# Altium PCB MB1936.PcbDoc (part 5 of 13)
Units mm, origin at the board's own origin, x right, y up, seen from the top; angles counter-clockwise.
Board outline 172 x 137 mm, 6 copper layers (Top Layer, Signal Layer 1, Signal Layer 2, Signal Layer 3, Signal Layer 4, Bottom Layer), stack 1.549 mm thick; 859 components, 672 nets, 3477 pads, 2222 vias.
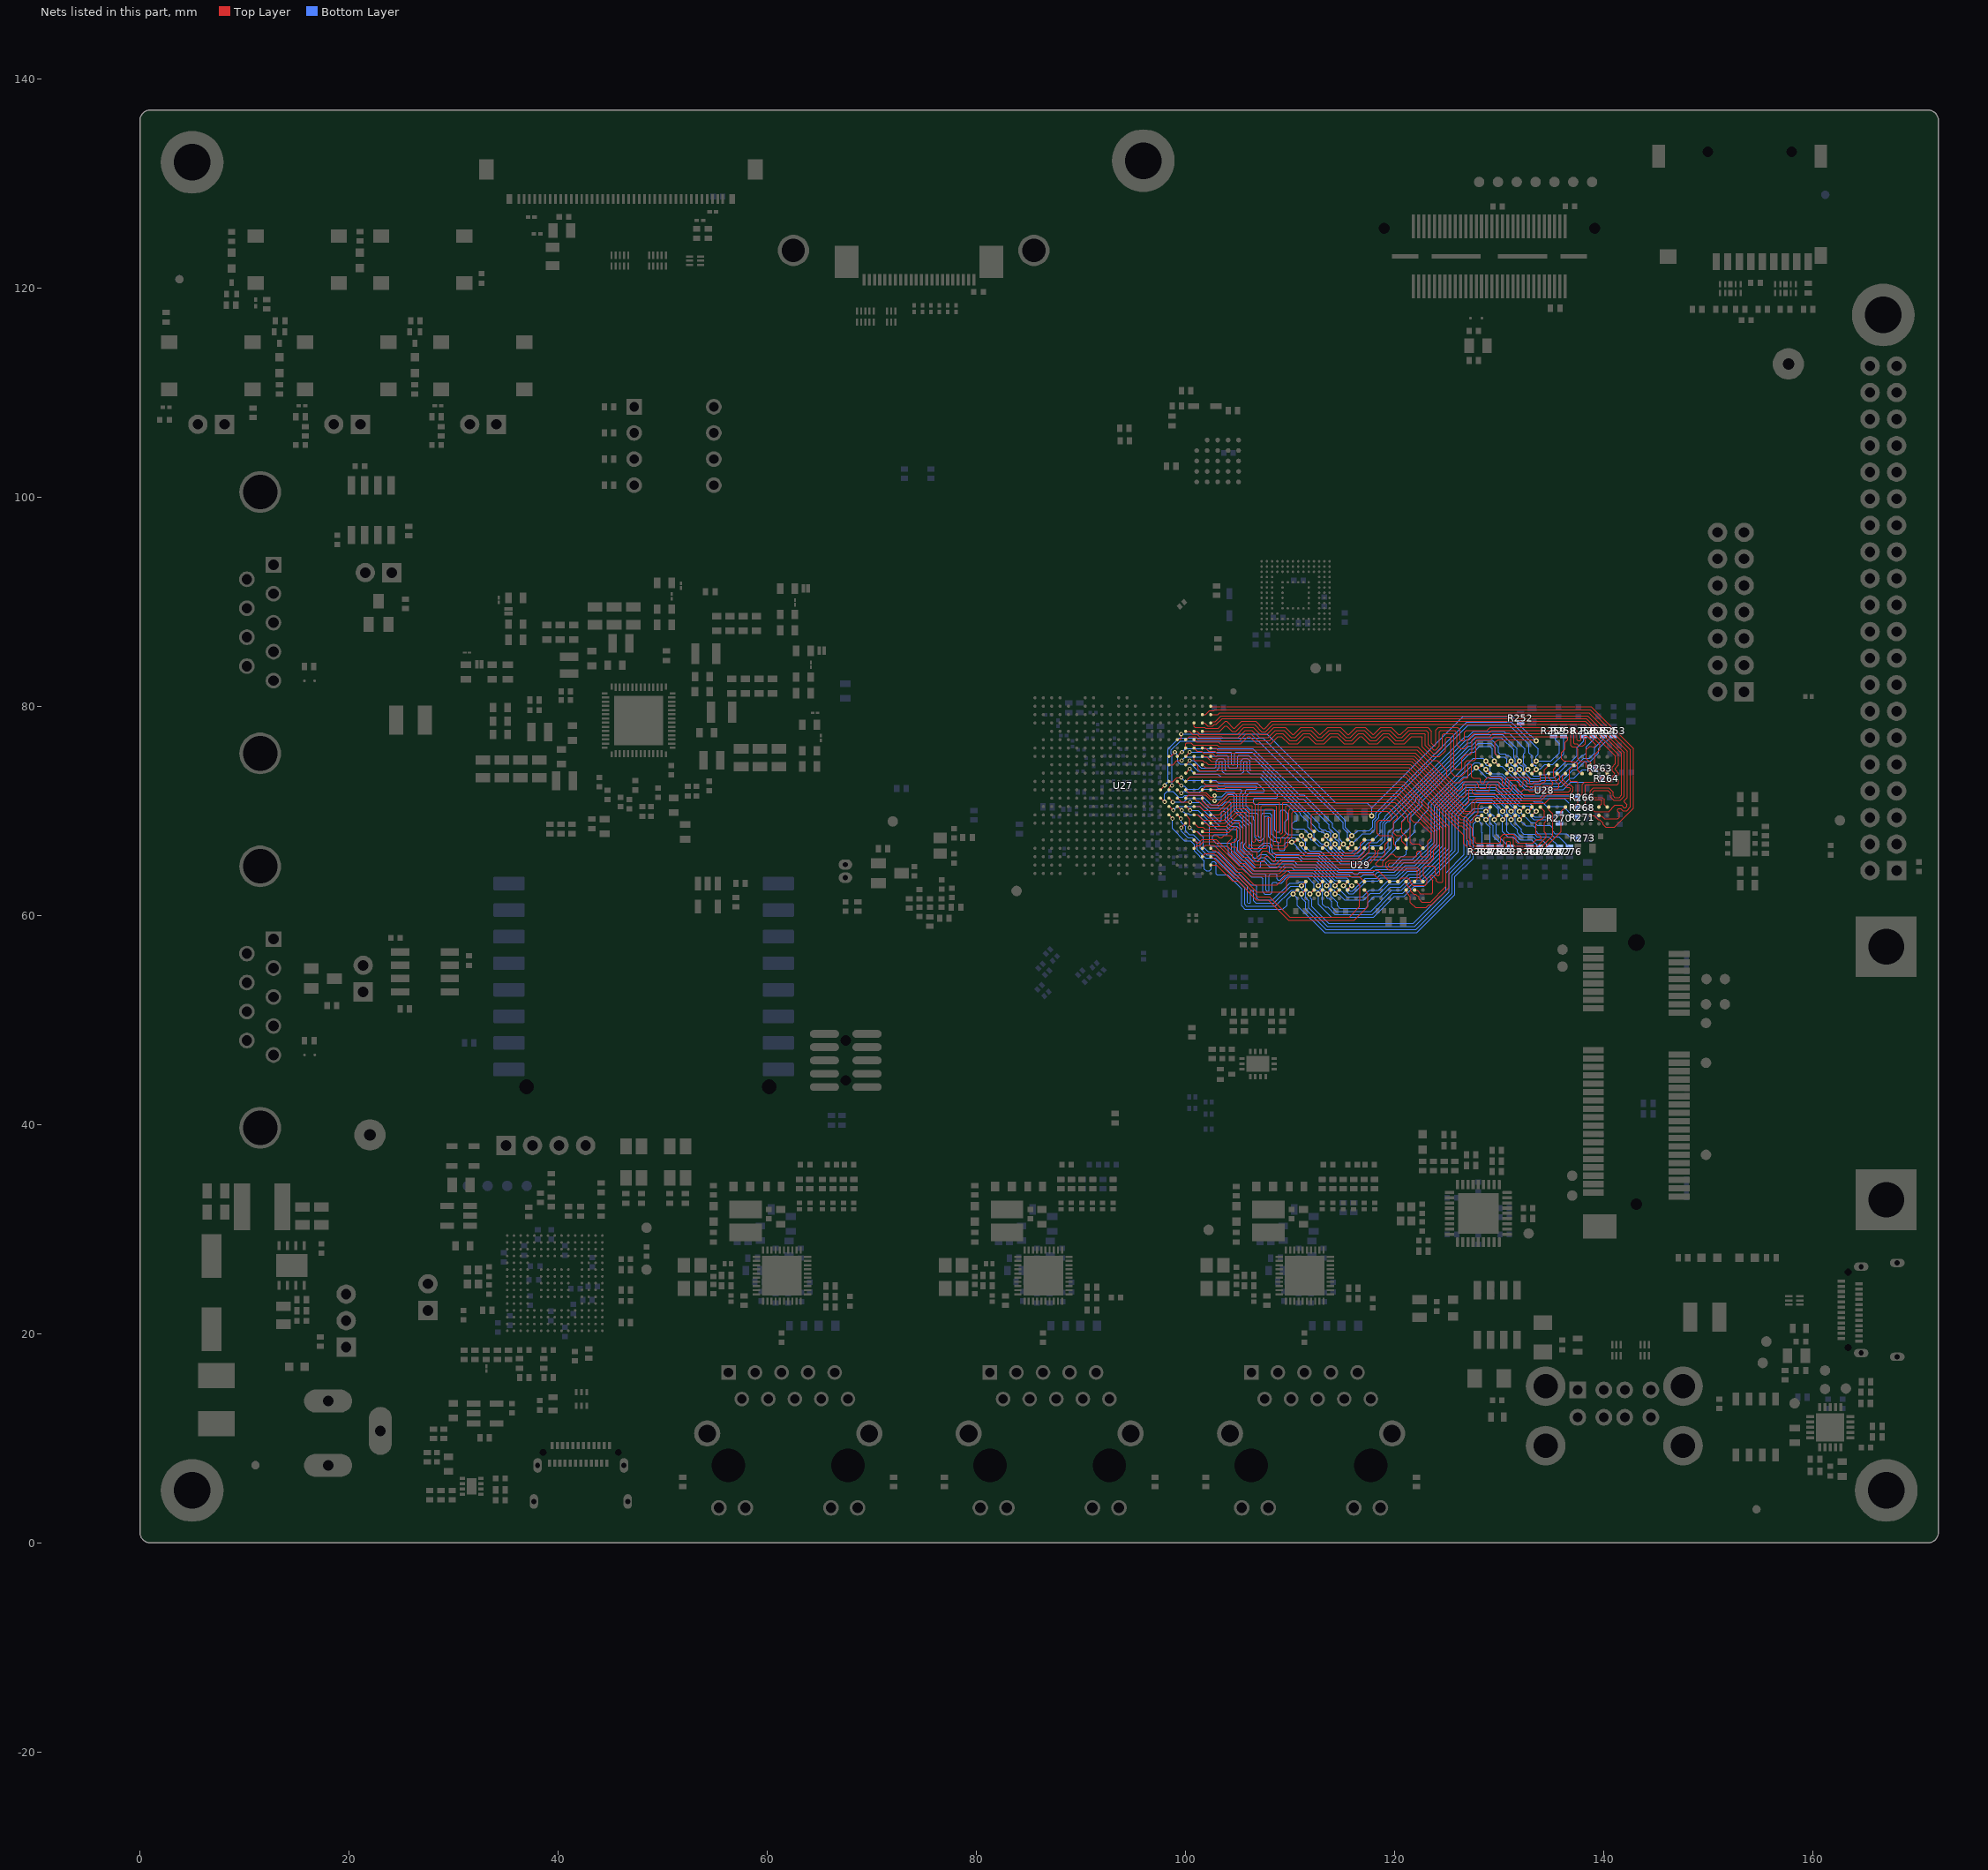
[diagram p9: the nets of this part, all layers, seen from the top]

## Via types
v1: diameter 0.55, hole 0.35, Top Layer to Bottom Layer, 1661 vias
v2: diameter 0.4, hole 0.2, Top Layer to Bottom Layer, tented both sides, 253 vias
v3: diameter 0.5, hole 0.2, Top Layer to Bottom Layer, 157 vias
v4: diameter 0.5, hole 0.25, Top Layer to Bottom Layer, 145 vias
v5: diameter 0.4, hole 0.2, Top Layer to Bottom Layer, 6 vias

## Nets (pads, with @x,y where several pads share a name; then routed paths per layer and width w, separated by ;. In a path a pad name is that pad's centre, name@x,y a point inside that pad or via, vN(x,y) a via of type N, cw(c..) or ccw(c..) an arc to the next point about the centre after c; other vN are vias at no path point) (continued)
DDR_A2: R268.1 U27.L18 U28.R3 U29.R3 | length 60.8
  Top Layer w0.09: U27.L18@99.2,72.8 v2(99.6,72.4) ; v4(111.1,66.825) 111.141,66.825 111.494,66.472 U29.R3@111.494,66.422 ; v4@128.732,73.928 128.772,73.928 129.125,73.575 U28.R3@129.125,73.55 U28.R3@129.125,73.525
  Bottom Layer w0.09: v2(99.6,72.4) 99.622,72.378 99.872,72.378 100.195,72.055 101.218,72.055 101.528,72.365 106.721,72.365 106.794,72.291 106.794,72.149 106.716,72.07 105.894,72.07 105.758,71.934 105.758,71.768 105.497,71.508 105.497,70.339 106.06,69.777 106.75,69.777 106.925,69.602 106.925,67.578 107.028,67.475 107.168,67.475 107.254,67.56 107.254,69.636 107.395,69.777 108.048,69.777 108.235,69.59 108.235,67.779 108.578,67.437 110.489,67.437 v4(111.1,66.825) 111.103,66.823 111.103,66.466 111.647,65.922 112.77,65.922 114.559,64.133 115.925,64.133 ; 115.925,64.132 116.116,63.94 116.457,63.94 116.65,64.133 117.958,64.133 118.21,64.385 ; 118.212,64.385 118.227,64.401 119.849,64.401 120.787,65.339 121.716,65.339 123.5,67.123 123.5,70.57 126.643,73.713 126.763,73.713 127.657,74.607 128.068,74.607 v4(128.725,73.95) 128.725,73.643 128.803,73.566 128.966,73.566 129.217,73.315 130.164,73.315 132.282,71.197 ; 132.28,71.195 136.23,71.195 137.125,70.3 R268.1@137.5,70.3
DDR_A3: R279.1 U27.P19 U28.N7 U29.N7 | length 56.9
  Top Layer w0.09: U27.P19@100,70.4 100.038,70.4 100.388,70.05 v2(100.425,70.05) ; v4(112.7,62.825) 112.724,62.825 113.094,63.195 U29.N7@113.094,63.222 ; v4@130.355,69.928 130.725,70.298 U28.N7@130.725,70.325
  Bottom Layer w0.09: v2(100.425,70.05) 101.175,70.05 102.992,68.234 103.762,68.234 103.993,68.003 103.993,67.765 103.94,67.713 102.738,67.713 102.575,67.55 102.575,67.25 102.898,66.927 104.298,66.927 104.415,66.81 104.415,65.963 106.421,63.958 107.549,63.958 107.679,63.828 107.679,62.403 107.759,62.322 107.922,62.322 107.975,62.375 107.975,63.81 108.123,63.958 108.606,63.958 108.725,63.839 108.725,63.481 108.822,63.384 109.037,63.384 109.49,63.837 112.024,63.837 112.7,63.161 v4(112.7,62.825) 112.7,62.775 112.9,62.575 112.9,62.384 113.104,62.18 113.104,61.046 113.37,60.78 113.595,60.78 114.275,60.1 117.854,60.1 119.854,62.1 120.773,62.1 121.731,63.059 122.66,63.059 125.781,66.18 125.781,69.627 127.244,71.09 129.246,71.09 130.325,70.011 v4(130.325,69.95) 130.325,69.9 130.513,69.713 130.513,69.588 130.6,69.5 130.6,69.434 130.72,69.314 130.72,68.021 130.939,67.803 131.443,67.803 132.021,67.225 133.086,67.225 133.376,66.935 133.389,66.935 133.39,66.934 133.417,66.934 133.825,66.525 R279.1@133.875,66.525
DDR_A4: R263.1 U27.H17 U28.N3 U29.N3 | length 60.3
  Top Layer w0.09: U27.H17@98.4,75.2 98.419,75.219 98.604,75.219 v2@98.98,75.595 ; U29.N3@113.094,66.422 113.094,66.47 113.449,66.825 v4(113.5,66.825) ; U28.N3@130.725,73.525 130.725,73.573 v4@131.08,73.928
  Bottom Layer w0.09: v2(98.98,75.6) 99.255,75.325 99.255,74.682 99.484,74.453 100.517,74.453 101.181,73.789 102.904,73.789 103.221,74.105 103.221,74.641 103.3,74.72 103.458,74.72 103.528,74.65 103.528,73.747 103.751,73.525 105.341,73.525 105.563,73.747 105.563,74.638 105.65,74.725 105.775,74.725 105.877,74.623 105.877,73.805 106.157,73.525 107.201,73.525 110.99,69.736 110.99,69.633 111.695,68.928 111.695,68.434 112.298,67.831 112.298,67.468 112.537,67.23 112.58,67.23 112.985,66.825 v4(113.5,66.825) 113.5,66.691 113.727,66.464 113.727,66.402 114.947,65.182 117.108,65.182 117.55,65.625 118.916,65.625 119.68,66.39 119.68,67.434 119.793,67.546 119.793,67.893 120.08,68.18 120.464,68.18 120.695,68.411 120.695,68.98 122.34,70.625 122.34,71.051 127.203,75.913 127.48,75.913 127.485,75.918 127.485,75.92 128,76.435 129.209,76.435 129.638,76.006 129.638,75.412 129.905,75.145 130.489,75.145 130.72,74.914 130.72,74.355 v4(131.125,73.95) 131.125,73.825 131.395,73.555 131.395,73.47 132.56,72.305 135.952,72.305 136.748,73.101 137.126,73.101 137.95,73.925 R263.1@139.2,73.925
DDR_A5: R282.1 U27.R19 U28.P8 U29.P8 | length 50.8
  Top Layer w0.09: U27.R19@100,69.6 100.4,69.2 v2(100.4,68.4) ; v4(111.9,62.025) 111.9,62.055 U29.P8@112.269,62.424 ; v4@129.532,69.158 U28.P8@129.901,69.527
  Bottom Layer w0.09: v2(100.4,68.4) 100.785,68.015 101.15,68.015 101.705,67.46 101.705,66.516 102.165,66.057 103.092,66.057 106.228,62.92 106.686,62.92 106.809,62.797 106.809,61.639 106.996,61.452 108.339,61.452 109.954,63.067 110.784,63.067 110.937,63.22 111.264,63.22 111.495,62.989 111.495,62.545 111.9,62.14 v4(111.9,62.025) 111.939,61.986 111.939,61.64 112.075,61.504 112.075,60.838 113.683,59.23 121.775,59.23 124.895,62.35 124.895,64.063 126.651,65.819 126.651,69.267 127.574,70.189 128.406,70.189 128.562,70.345 128.889,70.345 129.12,70.114 129.12,69.8 129.13,69.79 129.13,69.786 129.362,69.555 129.431,69.555 129.5,69.485 129.5,69.175 v4(129.525,69.15) 129.525,68.85 129.7,68.675 129.7,67.775 130.95,66.525 R282.1@131.025,66.525
DDR_A6: R264.1 U27.K19 U28.P2 U29.P2 | length 60.1
  Top Layer w0.09: U27.K19@100,73.6 v2(100.4,74) ; v4@111.896,67.62 112.269,67.247 112.294,67.247 112.375,67.166 112.35,67.166 U29.P2@112.294,67.222 ; v4@129.525,74.725 129.9,74.35 U28.P2@129.925,74.35
  Bottom Layer w0.09: v2(100.4,74) 100.4,73.99 100.891,73.499 103.108,73.499 103.372,73.235 107.081,73.235 108.8,71.516 108.8,71.292 108.708,71.2 106.6,71.2 106.5,71.1 106.5,70.747 106.6,70.647 109.669,70.647 110.7,69.616 110.7,69.096 110.648,69.043 110.488,69.043 110.199,68.754 110.199,68.412 110.361,68.25 111.315,68.25 v4@111.894,67.671 ; v4(111.9,67.625) 111.9,67.323 111.996,67.228 112.147,67.228 112.74,66.635 113.123,66.635 114.826,64.932 117.283,64.932 117.675,65.325 119.032,65.325 119.7,65.994 119.7,66 120.078,66.377 120.078,66.994 121.495,68.411 121.495,69.37 122.63,70.505 122.63,70.894 122.631,70.895 122.631,70.932 127.323,75.623 127.6,75.623 128.12,76.143 128.12,76.145 129.089,76.145 129.348,75.886 129.348,75.102 129.525,74.925 v4(129.525,74.75) 130.035,74.24 130.277,74.24 132.502,72.015 136.126,72.015 136.841,72.73 139.506,72.73 R264.1@139.75,72.975
DDR_A7: R275.1 U27.T19 U28.R8 U29.R8 | length 48.8
  Top Layer w0.09: v2(99.6,68.4) U27.T19@100,68.8 ; v4(111.1,62.025) U29.R8@111.5,62.425 ; v4@128.732,69.128 U28.R8@129.132,69.528
  Bottom Layer w0.09: v2(99.6,68.4) 99.607,68.393 99.607,68.059 100.231,67.435 100.628,67.435 101.125,66.938 101.125,66.276 101.924,65.477 102.823,65.477 105.649,62.65 105.649,61.035 105.812,60.872 108.587,60.872 ; 108.587,60.873 110.132,62.417 110.134,62.417 110.137,62.42 110.705,62.42 v4(111.1,62.025) ; v4@111.107,62.025 111.126,62.006 111.126,61.633 111.495,61.264 111.495,60.598 113.443,58.65 122.015,58.65 125.475,62.11 125.475,63.823 127.231,65.579 127.231,69.026 127.75,69.545 128.337,69.545 v4@128.725,69.157 ; v4@128.732,69.15 128.757,69.125 128.757,68.776 129.12,68.413 R275.1@129.12,66.53
  other v4: 128.725,69.15
DDR_A8: R266.1 U27.L17 U28.R2 U29.R2 | length 61.8
  Top Layer w0.09: U27.L17@98.4,72.8 98.783,72.8 99.158,73.175 v2(99.6,73.175) ; v4@111.094,67.622 U29.R2@111.494,67.222 ; v4@128.725,74.725 U28.R2@129.125,74.325
  Bottom Layer w0.09: v2(99.6,73.175) 99.856,72.919 102.868,72.919 103.132,72.655 106.841,72.655 107.525,71.971 107.525,71.833 107.473,71.78 106.18,71.78 105.787,71.388 105.787,70.46 106.18,70.067 108.458,70.067 108.525,70 108.525,68.156 108.694,67.988 108.975,67.988 109.075,68.088 109.075,69.967 109.175,70.067 109.429,70.067 109.805,69.691 109.805,69.23 109.519,68.944 109.519,68.027 109.814,67.732 110.873,67.732 110.983,67.622 v4@111.094,67.622 ; v4@111.14,67.576 111.14,67.293 111.213,67.22 111.264,67.22 111.5,66.984 111.5,66.525 111.854,66.172 112.873,66.172 114.662,64.383 117.693,64.383 118.001,64.691 119.716,64.691 120.655,65.63 120.864,65.63 121.105,65.871 121.105,66.189 121.175,66.259 121.175,67.25 121.905,67.98 121.905,68.589 122.038,68.721 122.038,68.788 122.55,69.3 122.55,69.465 123.21,70.125 123.21,70.654 123.211,70.655 123.211,70.691 127.538,75.018 128.433,75.018 128.7,74.75 128.7,74.425 128.775,74.35 128.957,74.35 129.13,74.176 129.13,73.77 129.345,73.555 130.263,73.555 132.372,71.446 136.654,71.446 136.85,71.25 R266.1@137.5,71.25
  other v4: 111.1,67.625 128.725,74.75
DDR_A9: R283.1 U27.R18 U28.R7 U29.R7 | length 52.8
  Top Layer w0.09: U27.R18@99.2,69.6 v2(99.55,69.25) ; v4(111.1,62.825) 111.494,63.218 U29.R7@111.494,63.222 ; v4@128.732,69.928 129.125,70.321 U28.R7@129.125,70.325
  Bottom Layer w0.09: v2(99.55,69.25) 99.595,69.205 99.595,68.9 100.026,68.47 100.026,68.05 100.346,67.73 100.66,67.73 100.665,67.725 100.749,67.725 101.415,67.058 101.415,66.396 102.044,65.767 102.943,65.767 105.939,62.77 105.939,61.236 106,61.175 106.169,61.175 106.221,61.228 ; 106.229,61.228 106.229,62.327 106.282,62.379 106.451,62.379 106.519,62.311 106.519,61.381 106.738,61.162 108.459,61.162 110.074,62.777 111.052,62.777 v4(111.1,62.825) 111.1,62.475 111.155,62.42 111.264,62.42 111.5,62.184 111.5,61.669 111.785,61.384 111.785,60.718 113.563,58.94 121.895,58.94 125.185,62.23 125.185,63.943 126.941,65.699 126.941,69.146 127.694,69.899 128.674,69.899 v4(128.725,69.95) ; v4@128.725,69.925 128.725,69.867 128.9,69.692 128.9,69.534 129.12,69.314 129.12,68.83 129.41,68.54 129.41,67.562 130.075,66.897 R283.1@130.075,66.525
DDR_A10: R254.1 U27.J17 U28.M3 U29.M3 | length 60.4
  Top Layer w0.09: U27.J17@98.4,74.4 98.783,74.4 99.183,74.8 v2(99.625,74.8) ; U29.M3@113.894,66.422 113.894,66.47 114.249,66.825 v4(114.3,66.825) ; U28.M3@131.525,73.55 131.525,73.573 v4@131.88,73.928
  Bottom Layer w0.09: v2(99.625,74.8) 99.632,74.8 99.977,75.145 102.361,75.145 102.433,75.217 102.977,75.217 103.06,75.3 103.933,75.3 104.108,75.125 104.108,74.2 104.204,74.105 104.886,74.105 104.983,74.203 104.983,75.2 105.088,75.305 106.016,75.305 106.348,74.973 106.573,74.973 112.805,68.741 112.805,68.411 113.037,68.18 113.34,68.18 113.5,68.02 113.68,68.02 113.903,67.798 113.903,67.304 114.263,66.943 114.263,66.825 v4(114.3,66.825) 114.3,66.536 115.154,65.682 116.653,65.682 117.621,66.65 118.575,66.65 119.1,67.175 119.1,68.745 119.325,68.97 119.509,68.97 121.76,71.221 121.76,71.291 126.963,76.493 127.238,76.493 127.76,77.015 130.179,77.015 131.39,75.804 131.39,75.441 131.391,75.043 131.52,74.914 131.52,74.53 131.75,74.3 131.75,74.2 131.925,74.025 v4(131.925,73.95) 131.925,73.836 132.22,73.541 132.22,73.466 132.851,72.835 133.987,72.835 134.037,72.885 135.554,72.885 136.864,74.195 137.255,74.195 138.075,75.015 138.599,75.015 139.12,75.536 139.12,76.034 139.95,76.864 R254.1@139.95,77.175
DDR_A11: R271.1 U27.M18 U28.T2 U29.T2 | length 59.6
  Top Layer w0.09: U27.M18@99.2,72 99.237,72 99.562,71.675 v2(99.6,71.675) ; v4(110.175,67) 110.423,67 110.647,67.224 U29.T2@110.694,67.224 ; v4@127.807,74.103 128.055,74.103 128.279,74.327 U28.T2@128.326,74.327
  Bottom Layer w0.09: v2(99.6,71.675) 99.6,71.677 99.79,71.867 99.973,71.867 100.089,71.751 101.324,71.751 101.648,72.075 105.226,72.075 105.375,71.925 105.375,71.796 105.207,71.628 105.207,70.219 105.94,69.487 106.405,69.487 106.52,69.372 106.52,69.168 106.635,69.053 106.635,67.458 106.908,67.185 107.288,67.185 107.579,67.475 107.579,69.402 107.664,69.487 107.858,69.487 107.945,69.4 107.945,67.505 108.35,67.1 108.75,67.1 108.855,66.995 108.855,66.376 109.015,66.215 109.412,66.215 109.519,66.322 109.519,66.856 109.662,67 v4(110.175,67) 110.216,67 110.625,66.59 110.625,66.507 111.46,65.672 112.666,65.672 114.455,63.883 115.625,63.883 115.858,63.65 116.782,63.65 117.015,63.883 118.118,63.883 118.33,64.095 ; 118.332,64.095 118.347,64.111 119.969,64.111 120.907,65.049 121.836,65.049 123.79,67.003 123.79,70.45 126.59,73.25 126.925,73.25 v4(127.8,74.125) 128.775,73.15 129,73.15 129.075,73.075 130.064,73.075 132.18,70.959 133.217,70.959 133.327,70.85 134.1,70.85 134.545,70.405 136.12,70.405 137.175,69.35 R271.1@137.5,69.35
DDR_A12: R277.1 U27.N18 U28.M7 U29.M7 | length 56.3
  Top Layer w0.09: U27.N18@99.2,71.2 99.575,70.825 v2(100.425,70.825) ; v4(113.5,62.825) 113.524,62.825 113.894,63.195 U29.M7@113.894,63.222 ; v4@131.132,69.928 131.155,69.928 131.525,70.298 U28.M7@131.525,70.325
  Bottom Layer w0.09: v2(100.425,70.825) 100.45,70.8 101.386,70.8 103.202,68.984 103.334,68.984 103.438,69.087 103.438,69.885 103.525,69.973 103.7,69.973 103.791,69.882 103.791,69.046 104.31,68.528 104.9,68.528 105.225,68.202 105.225,67.308 104.995,67.078 104.995,66.204 106.661,64.538 107.038,64.538 107.19,64.69 107.19,65.07 107.327,65.206 107.474,65.206 108.035,64.645 110.092,64.645 110.38,64.357 112.211,64.357 113.5,63.068 v4@113.5,62.882 ; v4(113.5,62.825) 113.711,62.614 113.711,62.373 113.895,62.189 113.895,61.84 114.505,61.23 114.505,60.911 114.737,60.68 117.214,60.68 117.45,60.916 117.45,61.234 118.042,61.825 118.704,61.825 119.579,62.7 120.553,62.7 121.491,63.639 122.42,63.639 125.2,66.419 125.2,69.866 127.004,71.67 129.488,71.67 131.125,70.033 v4(131.125,69.95) 131.35,69.725 131.35,69.556 131.522,69.385 131.522,68.795 132.105,68.211 132.105,67.986 132.337,67.755 133.377,67.755 133.617,67.515 133.629,67.515 133.63,67.514 134.746,67.514 135.735,66.525 R277.1@135.775,66.525
DDR_A13: R284.1 U27.R17 U28.T8 U29.T8 | length 51.4
  Top Layer w0.09: U27.R17@98.4,69.6 v2(98.75,69.25) ; v4(110.3,62.025) 110.3,62.055 U29.T8@110.669,62.424 ; v4@127.932,69.158 128.004,69.23 128.255,69.481 U28.T8@128.301,69.527
  Bottom Layer w0.09: v2(98.75,69.25) 98.75,68.29 99.895,67.145 100.456,67.145 100.835,66.765 100.835,66.156 101.804,65.187 101.804,64.422 101.985,64.242 102.274,64.242 102.453,64.42 102.453,64.976 102.602,65.125 102.764,65.125 102.907,64.982 102.907,63.977 103.017,63.867 104.022,63.867 105.359,62.53 105.359,60.908 105.685,60.582 109.315,60.582 109.698,60.965 109.698,61.503 110.22,62.025 v4(110.3,62.025) 110.705,61.62 110.705,60.936 113.282,58.36 122.135,58.36 125.765,61.99 125.765,63.703 127.521,65.459 127.521,68.734 127.925,69.138 v4(127.925,69.15) ; v4@127.925,69.125 128.323,68.728 128.323,67.936 128.375,67.884 128.375,66.725 R284.1@128.175,66.525
DDR_ACTN: R256.1 U27.H18 U28.L3 U29.L3 | length 55.5
  Top Layer w0.09: U27.H18@99.2,75.2 99.6,75.6 v2(99.65,75.6) ; U29.L3@114.694,66.422 114.694,66.47 115.049,66.825 v4(115.1,66.825) ; U28.L3@132.325,73.525 132.325,73.573 v4@132.68,73.928
  Bottom Layer w0.09: v2@99.658,75.6 100.003,75.945 106.429,75.945 110.879,71.495 111.313,71.495 114.055,68.753 114.055,68.429 114.703,67.781 114.703,67.279 115.1,66.882 115.1,66.755 115.656,66.2 116.288,66.2 117.318,67.23 117.944,67.23 118.618,67.904 118.618,68.838 119.084,69.304 119.084,69.435 126.722,77.073 126.998,77.073 127.52,77.595 130.42,77.595 130.598,77.417 130.942,77.417 132.47,75.889 132.47,75.561 132.325,75.416 132.325,74.517 132.56,74.282 132.56,74.177 132.725,74.012 v4(132.725,73.95) 132.725,73.852 133.262,73.315 133.788,73.315 133.948,73.475 134.475,73.475 134.703,73.703 135.361,73.703 136.433,74.775 136.919,74.775 137.425,75.281 137.425,76.024 138.05,76.65 R256.1@138.05,77.175
DDR_BA0: R253.1 U27.J19 U28.N2 U29.N2 | length 60.7
  Top Layer w0.09: U27.J19@100,74.4 v2(100.4,74.8) ; U29.N2@113.094,67.222 113.094,67.27 v4@113.424,67.6 ; U28.N2@130.725,74.325 130.725,74.373 v4@131.055,74.703
  Bottom Layer w0.09: v2(100.4,74.8) 100.409,74.791 100.756,74.791 101.468,74.079 102.784,74.079 102.931,74.225 102.931,74.761 103.18,75.01 103.578,75.01 103.818,74.77 103.818,73.94 103.943,73.815 105.166,73.815 105.273,73.922 105.273,74.758 105.53,75.015 105.895,75.015 106.167,74.743 106.167,73.925 106.277,73.815 107.322,73.815 111.985,69.151 111.985,68.804 112.77,68.02 112.928,68.02 112.958,67.99 113.135,67.99 v4(113.5,67.625) ; v4@113.5,67.6 113.5,67.322 113.603,67.22 113.664,67.22 113.901,66.983 113.901,66.666 114.05,66.516 114.05,66.433 115.051,65.432 116.862,65.432 117.383,65.952 118.833,65.952 119.39,66.51 119.39,67.906 119.905,68.421 119.905,68.81 122.05,70.955 122.05,71.171 127.083,76.203 127.358,76.203 127.88,76.725 129.329,76.725 129.928,76.126 129.928,75.572 130.05,75.45 130.542,75.45 130.662,75.33 130.871,75.33 131.101,75.1 131.101,74.923 131.125,74.899 v4(131.125,74.75) 131.125,74.425 131.205,74.345 131.289,74.345 131.52,74.114 131.52,73.78 132.705,72.595 135.744,72.595 137.054,73.905 137.376,73.905 138.196,74.725 138.719,74.725 139.512,75.518 139.512,75.933 140.15,76.572 140.15,76.59 140.235,76.675 140.299,76.675 140.799,77.175 R253.1@140.9,77.175
DDR_BA1: R280.1 U27.P18 U28.N8 U29.N8 | length 53.6
  Top Layer w0.09: U27.P18@99.2,70.4 99.237,70.4 99.588,70.05 v2(99.625,70.05) ; v4(112.7,62.025) 112.7,62.055 U29.N8@113.069,62.424 ; v4@130.332,69.158 U28.N8@130.701,69.527
  Bottom Layer w0.09: v2(99.625,70.05) 99.648,70.05 99.974,69.724 100.264,69.724 100.38,69.607 101.208,69.607 102.285,68.53 102.285,66.756 102.405,66.637 103.928,66.637 104.125,66.44 104.125,65.843 106.301,63.668 107.22,63.668 107.389,63.499 107.389,62.214 107.571,62.032 108.099,62.032 108.265,62.198 108.265,63.04 108.375,63.15 108.646,63.15 108.702,63.094 109.157,63.094 109.71,63.647 111.637,63.647 112.299,62.985 112.299,62.531 112.428,62.402 112.613,62.402 112.7,62.315 v4(112.7,62.025) 112.7,61.033 113.924,59.81 117.974,59.81 119.974,61.81 120.893,61.81 121.852,62.769 122.78,62.769 126.071,66.06 126.071,69.507 127.365,70.8 129.234,70.8 129.92,70.114 129.92,69.796 130.162,69.555 130.245,69.555 130.3,69.5 130.3,69.175 v4(130.325,69.15) 130.325,68.006 130.832,67.5 131.335,67.5 131.9,66.935 132.44,66.935 132.85,66.525 R280.1@132.925,66.525
DDR_BG0: R255.1 U27.H19 U28.M2 U29.M2 | length 57.6
  Top Layer w0.09: U27.H19@100,75.2 v2(100.4,75.6) ; U29.M2@113.894,67.222 113.894,67.27 114.249,67.625 v4(114.3,67.625) ; U28.M2@131.525,74.325 131.525,74.373 v4@131.88,74.728
  Bottom Layer w0.09: v2(100.4,75.6) 104.298,75.6 104.398,75.5 104.398,74.479 104.482,74.395 104.612,74.395 104.693,74.476 104.693,75.468 104.825,75.6 106.357,75.6 110.832,71.125 111.233,71.125 113.703,68.655 113.703,68.303 v4@114.341,67.666 ; v4(114.3,67.625) 114.3,67.306 114.387,67.22 114.464,67.22 114.7,66.984 114.7,66.49 115.258,65.932 116.463,65.932 117.471,66.94 118.315,66.94 118.857,67.482 118.857,68.798 126.843,76.783 127.118,76.783 127.64,77.305 130.299,77.305 131.68,75.924 131.68,75.561 ; 131.681,75.561 131.681,75.163 131.81,75.034 131.81,74.976 131.925,74.861 v4(131.925,74.75) 131.925,74.47 132.045,74.35 132.139,74.35 132.32,74.168 132.32,73.786 132.317,73.783 133.025,73.075 133.888,73.075 133.988,73.175 135.244,73.175 136.554,74.485 137.135,74.485 137.955,75.305 138.089,75.305 138.32,75.536 138.32,76.107 139,76.787 R255.1@139,77.175
DDR_CASN: R278.1 U27.P17 U28.M8 U29.M8 | length 53.7
  Top Layer w0.09: U27.P17@98.4,70.4 98.45,70.4 98.8,70.05 v2@98.85,70.05 ; v4(113.5,62.025) 113.5,62.055 U29.M8@113.869,62.424 ; v4@131.132,69.158 U28.M8@131.501,69.527
  Bottom Layer w0.09: v2@98.85,70.05 99.2,70.4 101.376,70.4 103.252,68.524 103.904,68.524 104.19,68.238 104.78,68.238 104.935,68.082 104.935,67.439 104.705,67.209 104.705,66.084 106.541,64.248 109.797,64.248 109.95,64.095 112.12,64.095 113.095,63.119 113.095,62.557 v4@113.441,62.211 ; v4@113.449,62.203 v4@113.441,62.211 ; R278.1@134.825,66.525 134.788,66.525 134.089,67.224 133.51,67.224 133.509,67.225 133.497,67.225 133.207,67.515 132.141,67.515 131.753,67.903 131.725,67.93 131.725,68.175 131.125,68.775 v4(131.125,69.15) 131.132,69.156 131.132,69.506 131.083,69.555 130.962,69.555 130.73,69.786 130.73,69.795 130.72,69.805 130.72,70.134 129.474,71.38 127.124,71.38 125.49,69.746 125.49,66.299 122.54,63.349 121.611,63.349 120.653,62.39 119.734,62.39 117.734,60.39 114.395,60.39 113.997,60.789 113.997,61.287 113.664,61.62 113.555,61.62 113.5,61.675 v4(113.5,62.025) 113.441,62.084 v4@113.441,62.211
  other v2: 98.825,70.05
DDR_CKE: R259.1 U27.M16 U28.K2 U29.K2 | length 57.3
  Top Layer w0.09: U27.M16@97.6,72 97.6,72.012 98,72.413 v2(98,72.425) ; U29.K2@115.5,67.225 v4(115.9,67.625) ; U28.K2@133.132,74.357 v4(133.525,74.75)
  Bottom Layer w0.09: v2(98,72.425) 98.345,72.77 98.345,75.92 99.386,76.961 107.381,76.961 115.278,69.064 115.278,68.398 115.9,67.776 v4(115.9,67.625) 115.975,67.625 116.45,68.1 117.584,68.1 117.9,68.416 117.9,69.065 118.215,69.379 118.215,69.796 126.896,78.477 131.132,78.477 133.72,75.889 133.72,75.392 133.525,75.197 v4(133.525,74.75) 134.965,74.75 135.75,75.535 135.75,76.4 135.375,76.775 135.375,77 R259.1@135.2,77.175
DDR_CLK_N: R270.2 U27.M19 U28.K8 U29.K8 | length 53.7
  Top Layer w0.09: U27.M19@100,72 100.295,71.705 101.964,71.705 102.369,71.3 102.625,71.3 v2(102.775,71.45) ; U29.K8@115.494,62.422 115.494,62.472 115.847,62.825 v4(115.9,62.825) ; U28.K8@133.125,69.525 U28.K8@133.125,69.55 133.125,69.575 133.478,69.928 v4@133.532,69.928
  Bottom Layer w0.09: v2(102.775,71.45) 102.859,71.45 102.981,71.328 103.454,71.328 103.91,71.785 104.607,71.785 104.917,71.475 104.917,70.099 106.345,68.671 106.345,66.508 106.489,66.365 106.9,66.365 107.435,66.9 108.025,66.9 108.287,66.638 108.287,66.089 108.563,65.813 110.813,65.813 111.243,65.383 112.6,65.383 114.397,63.586 115.411,63.586 115.616,63.38 115.616,63.03 115.794,62.852 115.794,62.764 115.614,62.584 115.614,62.427 115.729,62.312 115.96,62.312 117.201,63.553 118.301,63.553 118.569,63.821 120.089,63.821 121.027,64.759 121.956,64.759 124.08,66.883 124.08,70.33 126.54,72.79 129.915,72.79 131.986,70.719 132.938,70.719 133.232,70.425 133.232,70.22 133.502,69.95 v4(133.525,69.95) 133.25,69.675 133.25,69.534 133.388,69.396 135.392,69.396 135.721,69.725 R270.2@135.75,69.725
DDR_CLK_P: R270.1 U27.N19 U28.K7 U29.K7 | length 53.6
  Top Layer w0.09: U27.N19@100,71.2 100.325,71.525 101.89,71.525 102.315,71.1 102.625,71.1 v2(102.775,70.95) ; v4(115.1,62.825) 115.147,62.825 115.494,63.172 U29.K7@115.494,63.222 ; v4@132.778,69.928 133.125,70.275 U28.K7@133.125,70.325
  Bottom Layer w0.09: v2(102.775,70.95) 102.855,70.95 102.983,71.078 103.557,71.078 104.014,71.535 104.504,71.535 104.667,71.371 104.667,69.996 106.095,68.568 106.095,66.405 106.385,66.115 107.004,66.115 107.539,66.65 107.921,66.65 108.037,66.535 108.037,65.985 108.459,65.563 110.709,65.563 111.139,65.133 112.496,65.133 114.293,63.336 115.307,63.336 115.366,63.277 115.366,63.03 v4@115.194,62.857 ; v4(115.1,62.825) 115.127,62.825 115.364,62.589 115.364,62.324 115.625,62.062 116.063,62.062 117.304,63.303 118.404,63.303 118.672,63.571 120.193,63.571 121.131,64.509 122.06,64.509 124.33,66.779 124.33,70.227 126.644,72.54 129.811,72.54 131.882,70.469 132.834,70.469 132.982,70.321 132.982,70.206 v4(132.725,69.95) 133,69.675 133,69.43 133.285,69.146 135.382,69.146 135.703,68.825 R270.1@135.75,68.825
DDR_CSN: R273.1 U27.N16 U28.L7 U29.L7 | length 57.9
  Top Layer w0.09: U27.N16@97.6,71.2 97.625,71.2 97.975,70.85 v2(98,70.85) ; v4(114.3,62.825) 114.332,62.825 114.669,63.163 U29.L7@114.669,63.224 ; v4@131.963,69.928 132.301,70.266 U28.L7@132.301,70.327
  Bottom Layer w0.09: v2(98,70.85) 98,71.6 98.25,71.85 98.8,71.85 99.352,71.298 99.779,71.298 99.941,71.46 101.546,71.46 102.453,70.553 103.528,70.553 103.8,70.825 104.25,70.825 104.371,70.704 104.371,69.286 104.55,69.108 105.14,69.108 105.805,68.443 105.805,66.98 105.575,66.75 105.575,66.444 106.54,65.479 106.78,65.479 107.125,65.825 107.675,65.825 108.275,65.225 110.332,65.225 110.7,64.857 112.418,64.857 114.3,62.975 v4(114.3,62.825) 114.3,62.775 114.65,62.425 114.754,62.425 115.407,61.772 116.937,61.772 117.57,62.405 118.464,62.405 119.339,63.28 120.312,63.28 121.251,64.219 122.18,64.219 124.62,66.659 124.62,70.106 126.764,72.25 129.653,72.25 131.368,70.535 131.911,69.991 131.911,69.978 131.925,69.964 v4(131.925,69.95) 133.036,68.839 133.4,68.839 133.632,68.607 134.35,68.607 ; 134.35,68.606 134.853,68.606 135.095,68.364 135.095,68.046 135.337,67.805 136.42,67.805 136.85,67.375 R273.1@137.55,67.375
DDR_DQ0: U27.W22 U29.F7 | length 18.5
  Top Layer w0.09: U27.W22@102.4,66.4 102.615,66.185 102.82,66.185 104.862,64.144 105.339,64.144 106.556,62.927 108.753,62.927 109.836,64.01 117.908,64.01 U29.F7@118.682,63.237
DDR_DQ1: U27.Y21 U29.H7 | length 18.5
  Top Layer w0.09: U27.Y21@101.6,65.6 101.6,65.628 101.867,65.895 102.7,65.895 104.741,63.854 105.219,63.854 106.826,62.246 109.511,62.246 109.669,62.405 109.669,63.377 110.012,63.72 116.596,63.72 U29.H7@117.094,63.222
DDR_DQ2: U27.Y22 U29.J7 | length 19.6
  Top Layer w0.09: U27.Y22@102.4,65.6 102.419,65.581 102.604,65.581 104.621,63.564 105.098,63.564 106.884,61.778 108.022,61.778 109.953,59.847 115.648,59.847 116.651,60.851 116.651,61.417 116.695,61.461 116.695,62.82 U29.J7@116.294,63.222
DDR_DQ3: U27.AA22 U29.H8 | length 19.5
  Top Layer w0.09: U27.AA22@102.4,64.8 102.975,64.8 104.501,63.274 104.978,63.274 106.764,61.488 107.902,61.488 109.843,59.547 116.149,59.547 117.453,60.851 117.453,62.063 U29.H8@117.094,62.422
DDR_DQ4: U27.T21 U29.J3 | length 20
  Top Layer w0.09: U27.T21@101.6,68.8 101.942,68.8 102.237,68.505 103.899,68.505 104.992,69.599 105.381,69.599 105.501,69.478 105.501,66.319 105.686,66.134 106.676,66.134 106.835,65.974 106.835,65.53 106.934,65.432 107.071,65.432 107.232,65.593 107.232,65.957 107.413,66.137 107.785,66.137 108.072,65.85 108.382,65.85 108.536,66.003 115.875,66.003 U29.J3@116.294,66.422
DDR_DQ5: U27.T20 U29.H2 | length 22.2
  Top Layer w0.09: U27.T20@100.8,68.8 101.182,68.418 101.67,68.418 101.873,68.215 104.019,68.215 104.777,68.973 105.038,68.973 105.139,68.872 105.139,68.517 105.211,68.445 105.211,66.198 105.566,65.844 106.371,65.844 106.423,65.791 106.423,65.463 106.744,65.142 107.523,65.142 107.576,65.195 107.576,65.527 107.706,65.658 107.848,65.658 108.364,65.142 108.498,65.142 108.612,65.256 108.612,65.628 108.697,65.713 116.104,65.713 116.735,66.345 116.735,66.864 U29.H2@117.094,67.222
DDR_DQ6: U27.U21 U29.H3 | length 20.3
  Top Layer w0.09: U27.U21@101.604,68.004 101.682,67.925 104.139,67.925 104.682,68.468 104.778,68.468 104.921,68.325 104.921,67.221 104.7,67 104.463,67 104.315,66.852 104.315,66.684 104.462,66.537 104.773,66.537 104.888,66.422 104.888,66.111 105.446,65.554 105.923,65.554 106.624,64.852 108.618,64.852 109.189,65.423 116.482,65.423 117.094,66.035 U29.H3@117.094,66.422
DDR_DQ7: U27.U20 U29.G2 | length 21.4
  Top Layer w0.09: U27.U20@100.8,68 101.078,68 101.452,67.626 103.005,67.626 103.231,67.4 103.475,67.4 103.7,67.626 104.375,67.626 104.428,67.573 104.428,67.375 104.025,66.972 104.025,66.564 105.326,65.264 105.803,65.264 106.504,64.562 108.738,64.562 109.309,65.133 116.602,65.133 117.544,66.074 117.544,66.872 U29.G2@117.894,67.222
DDR_DQ8: U27.M21 U29.B8 | length 35.2
  Top Layer w0.09: U27.M21@101.6,72 101.903,72.303 102.947,72.303 103.083,72.168 103.776,72.168 103.826,72.217 120.651,72.217 124.615,68.253 124.615,63.246 124.515,63.146 124.15,63.146 123.994,63.303 123.994,63.472 123.614,63.852 123.54,63.852 123.378,63.69 123.378,63.616 123.645,63.349 123.645,62.17 123.55,62.075 122.461,62.075 122.151,62.386 121.93,62.386 U29.B8@121.894,62.422
DDR_DQ9: U27.M22 U29.D7 | length 35.2
  Top Layer w0.09: U27.M22@102.4,72 102.84,72 102.963,71.878 103.896,71.878 103.946,71.927 103.961,71.927 120.531,71.927 124.325,68.133 124.325,63.934 124.185,63.794 124.082,63.794 123.893,63.982 123.893,64.552 123.715,64.73 122.952,64.73 122.769,64.547 122.769,63.797 123.094,63.471 123.094,63.063 122.908,62.877 121.751,62.877 121.474,63.154 121.474,63.339 121.241,63.573 120.644,63.573 U29.D7@120.294,63.222
DDR_DQ10: U27.L21 U29.C7 | length 36.4
  Top Layer w0.09: U27.L21@101.6,72.8 101.9,72.5 103.16,72.5 103.203,72.458 103.656,72.458 103.706,72.507 120.771,72.507 124.905,68.373 124.905,62.771 123.411,61.277 122.596,61.277 122.321,61.552 122.321,61.708 122.007,62.022 121.806,62.022 121.521,62.307 121.521,62.523 121.094,62.951 U29.C7@121.094,63.222
DDR_DQ11: U27.L22 U29.C8 | length 36.5
  Top Layer w0.09: U27.L22@102.403,72.797 120.891,72.797 125.195,68.493 125.195,62.651 123.531,60.987 123.257,60.987 123.025,60.755 121.984,60.755 121.984,60.758 121.507,61.234 121.507,61.777 121.15,62.134 121.15,62.375 U29.C8@121.1,62.425
DDR_DQ12: U27.T22 U29.D3 | length 35.7
  Top Layer w0.09: U27.T22@102.4,68.8 103.783,68.8 104.872,69.889 105.737,69.889 105.791,69.835 105.791,66.585 105.949,66.427 107.716,66.427 107.827,66.538 107.827,69.263 107.91,69.347 108.01,69.347 108.123,69.233 108.123,66.54 108.296,66.367 109.46,66.367 109.78,66.687 109.78,67.164 110.164,67.547 110.164,69.788 110.313,69.937 119.279,69.937 119.719,69.497 119.719,69.239 119.587,69.108 118.533,69.108 118.305,68.88 118.305,67.858 118.541,67.622 119.665,67.622 119.924,67.363 119.924,66.792 U29.D3@120.294,66.422
DDR_DQ13: U27.R20 U29.C3 | length 37.4
  Top Layer w0.09: U27.R20@100.8,69.6 101.138,69.6 101.636,69.102 103.675,69.102 104.765,70.192 105.844,70.192 106.081,69.955 106.081,66.825 106.188,66.717 107.424,66.717 107.537,66.83 107.537,70.029 107.653,70.145 108.296,70.145 108.413,70.028 108.413,66.754 108.51,66.657 109.34,66.657 109.49,66.807 109.49,67.284 109.874,67.667 109.874,70.049 110.052,70.227 119.483,70.227 120.263,69.447 120.269,69.447 120.269,69.337 119.902,68.97 119.902,67.875 120.149,67.628 120.538,67.628 120.694,67.472 120.694,67.085 121.08,66.698 121.08,66.436 U29.C3@121.094,66.422
DDR_DQ14: U27.R21 U29.C2 | length 36.8
  Top Layer w0.09: U27.R21@101.6,69.6 101.893,69.6 102.189,69.304 103.346,69.304 104.56,70.517 106.284,70.517 106.371,70.431 106.371,67.089 106.453,67.007 106.566,67.007 106.661,67.102 106.661,67.233 106.737,67.309 106.852,67.309 106.957,67.204 106.957,67.082 107.031,67.007 107.158,67.007 107.247,67.096 107.247,70.431 107.333,70.517 108.633,70.517 108.703,70.447 108.703,67.035 108.791,66.947 109.031,66.947 109.121,67.037 109.121,67.358 109.584,67.821 109.584,70.439 109.662,70.517 119.769,70.517 120.994,69.292 120.994,69.186 120.704,68.897 120.704,67.924 121.094,67.534 U29.C2@121.094,67.222
DDR_DQ15: U27.R22 U29.A3 | length 35.9
  Top Layer w0.09: U27.R22@102.4,69.6 103.232,69.6 104.44,70.807 106.441,70.807 106.661,70.587 106.661,67.682 106.743,67.599 106.876,67.599 106.957,67.68 106.957,70.705 107.059,70.807 108.94,70.807 108.993,70.754 108.993,67.867 109.046,67.814 109.167,67.814 109.294,67.941 109.294,70.754 109.346,70.807 120.01,70.807 121.286,69.532 121.286,68.986 121.495,68.776 121.495,66.99 121.665,66.82 122.296,66.82 U29.A3@122.694,66.422
DDR_DQ16: U27.D20 U28.D7 | length 52.3
  Top Layer w0.09: U27.D20@100.8,78.4 100.8,78.074 100.912,77.962 ; 100.913,77.963 101.838,77.963 101.908,77.892 103.143,77.892 103.791,78.54 103.925,78.54 104.573,77.892 104.712,77.892 105.36,78.54 106.715,78.54 107.399,77.856 107.546,77.856 108.231,78.54 138.22,78.54 141.412,75.348 141.412,74.373 ; U28.D7@137.925,70.35 137.925,70.366 138.23,70.67 138.23,72.412 138.282,72.465 141.261,72.465 141.413,72.617 141.413,72.863 141.236,73.04 141.236,73.285 141.413,73.462 141.413,73.593 141.093,73.913 141.093,74.052 141.413,74.372
DDR_DQ17: U27.C22 U28.C7 | length 50.9
  Top Layer w0.09: U27.C22@102.4,79.2 103.106,79.2 103.277,79.37 138.564,79.37 142.243,75.691 142.243,71.27 141.949,70.976 141.949,70.826 142.191,70.585 142.191,70.427 142.067,70.304 141.924,70.304 141.703,70.525 141.072,70.525 140.468,69.921 139.13,69.921 U28.C7@138.725,70.325
DDR_DQ18: U27.C21 U28.B8 | length 52.6
  Top Layer w0.09: U27.C21@101.6,79.2 101.897,79.2 102.272,79.575 102.725,79.575 102.811,79.66 138.684,79.66 142.533,75.812 142.533,70.359 142.188,70.014 141.804,70.014 141.631,70.187 141.402,70.187 141.318,70.103 141.318,69.932 141.47,69.78 141.47,69.366 141.332,69.228 140.047,69.228 139.78,69.495 139.58,69.495 U28.B8@139.525,69.55
DDR_DQ19: U27.B22 U28.C8 | length 53.2
  Top Layer w0.09: U27.B22@102.4,80 102.45,79.95 138.804,79.95 139.04,79.715 142.823,75.932 142.823,70.239 141.014,68.43 140.193,68.43 139.93,68.693 139.93,68.798 139.568,69.16 139.463,69.16 139.073,69.55 U28.C8@138.725,69.55
DDR_DQ20: U27.F20 U28.D3 | length 54.2
  Top Layer w0.09: U27.F20@100.8,76.8 101.025,76.575 103.14,76.575 103.309,76.406 105.277,76.406 105.961,77.09 106.115,77.09 106.799,76.406 108.147,76.406 108.831,77.09 109.181,77.09 109.865,76.406 110.711,76.406 111.395,77.09 111.74,77.09 112.424,76.406 113.261,76.406 113.945,77.09 114.465,77.09 115.149,76.406 115.986,76.406 116.67,77.09 116.843,77.09 117.527,76.406 118.352,76.406 119.036,77.09 119.305,77.09 119.989,76.406 120.936,76.406 121.62,77.09 122.6,77.09 122.646,77.045 122.646,76.1 123.574,75.172 124.284,75.172 124.865,75.753 124.865,76.89 125,77.025 125.225,77.025 125.376,76.875 125.376,73.68 125.721,73.335 126.42,73.335 126.7,73.615 126.7,74.601 126.925,74.825 127.6,74.825 127.755,74.98 127.755,76.67 127.881,76.796 129.196,76.796 129.49,77.09 136.46,77.09 136.545,77.005 136.545,76.795 136.3,76.55 136.3,75.9 135.95,75.55 135.95,74.96 136.15,74.761 136.786,74.761 136.852,74.695 137.323,74.695 137.47,74.548 137.47,73.897 137.818,73.55 U28.D3@137.925,73.55
DDR_DQ21: U27.F19 U28.C3 | length 54.6
  Top Layer w0.09: U27.F19@100,76.8 100.039,76.8 100.339,77.1 100.924,77.1 101.199,76.825 103.3,76.825 103.429,76.696 105.157,76.696 105.841,77.38 106.235,77.38 106.919,76.696 108.027,76.696 108.711,77.38 109.301,77.38 109.985,76.696 110.591,76.696 111.275,77.38 111.86,77.38 112.544,76.696 113.141,76.696 113.825,77.38 114.585,77.38 115.269,76.696 115.866,76.696 116.55,77.38 116.963,77.38 117.647,76.696 118.232,76.696 118.916,77.38 119.425,77.38 120.109,76.696 120.816,76.696 121.5,77.38 122.821,77.38 122.936,77.265 122.936,76.22 123.694,75.462 123.962,75.462 124.575,76.075 124.575,77.25 124.706,77.38 125.52,77.38 125.666,77.235 125.666,74.1 125.816,73.95 126.285,73.95 126.41,74.075 126.41,74.993 126.793,75.375 127.25,75.375 127.4,75.525 127.4,76.75 127.736,77.086 129.076,77.086 129.37,77.38 136.745,77.38 136.835,77.29 136.835,76.785 ; 136.835,76.765 136.835,76.24 136.98,76.095 137.289,76.095 137.52,75.864 137.52,75.848 137.527,75.842 137.527,75.644 137.528,75.642 137.528,74.983 137.537,74.974 137.537,74.964 137.768,74.733 137.778,74.733 137.781,74.73 138.161,74.73 138.325,74.566 138.325,74.188 138.712,73.801 U28.C3@138.712,73.539
DDR_DQ22: U27.E19 U28.C2 | length 54
  Top Layer w0.09: U27.E19@100,77.6 100.376,77.6 100.676,77.3 101.117,77.3 101.317,77.1 103.435,77.1 103.549,76.986 105.036,76.986 105.721,77.67 106.355,77.67 107.039,76.986 107.907,76.986 108.591,77.67 109.421,77.67 110.105,76.986 110.47,76.986 111.155,77.67 111.98,77.67 112.665,76.986 113.02,76.986 113.705,77.67 114.705,77.67 115.39,76.986 115.745,76.986 116.43,77.67 117.083,77.67 117.767,76.986 118.111,76.986 118.796,77.67 119.545,77.67 120.229,76.986 120.695,76.986 121.38,77.67 123.009,77.67 123.226,77.454 123.226,76.34 123.741,75.825 123.915,75.825 124.275,76.185 124.275,77.55 124.396,77.67 125.75,77.67 125.957,77.464 125.957,76.268 126.289,75.937 126.673,75.937 126.962,76.226 126.962,76.77 127.568,77.376 128.956,77.376 129.25,77.67 136.955,77.67 137.125,77.5 137.125,76.462 137.2,76.387 137.417,76.387 137.608,76.196 138,76.196 138.225,76.421 138.225,76.75 138.09,76.885 138.09,77.065 138.155,77.13 138.4,77.13 139.204,76.326 139.204,76.204 139.095,76.095 138.925,76.095 138.845,76.175 138.642,76.175 138.323,75.856 138.323,74.978 138.568,74.733 138.63,74.733 138.725,74.637 U28.C2@138.725,74.35
DDR_DQ23: U27.E20 U28.A3 | length 53.5
  Top Layer w0.09: U27.E20@100.8,77.6 101.1,77.6 101.4,77.3 104.94,77.3 105.601,77.96 106.475,77.96 107.159,77.276 107.787,77.276 108.471,77.96 109.541,77.96 110.225,77.276 110.35,77.276 111.035,77.96 112.1,77.96 112.785,77.276 112.9,77.276 113.585,77.96 114.825,77.96 115.51,77.276 115.625,77.276 116.31,77.96 117.203,77.96 117.887,77.276 117.991,77.276 118.676,77.96 119.665,77.96 120.349,77.276 120.575,77.276 121.26,77.96 123.164,77.96 123.516,77.608 123.516,76.46 123.778,76.198 123.878,76.198 123.95,76.27 123.95,77.725 124.186,77.96 125.99,77.96 126.247,77.703 126.247,76.798 126.35,76.695 126.592,76.695 126.672,76.775 126.672,77.499 126.839,77.666 128.836,77.666 129.13,77.96 137.115,77.96 137.425,77.65 137.425,76.788 137.494,76.719 137.719,76.719 137.8,76.8 137.8,77.3 137.92,77.42 138.52,77.42 139.625,76.315 139.625,75.862 139.137,75.374 139.137,74.086 139.278,73.945 139.905,73.945 U28.A3@140.325,73.525
DDR_DQ24: U27.G19 U28.J3 | length 42.1
  Top Layer w0.09: U27.G19@100,76 100,76.4 100.1,76.5 100.505,76.5 100.71,76.295 103.009,76.295 103.188,76.116 122.219,76.116 123.543,74.793 124.058,74.793 125.002,73.848 125.002,73.333 125.661,72.675 126.209,72.675 126.644,73.11 126.925,73.11 127,73.185 127,74.388 127.086,74.474 127.259,74.474 127.362,74.37 127.362,73.248 127.5,73.11 128.09,73.11 128.2,73 128.2,72.735 128.32,72.615 128.485,72.615 128.625,72.755 128.625,72.9 128.925,73.2 130.125,73.2 130.306,73.02 130.306,72.475 130.346,72.435 130.525,72.435 130.625,72.535 130.625,73.046 130.779,73.2 132.748,73.2 132.9,73.048 132.9,72.67 133.01,72.56 ; 133.011,72.56 133.14,72.56 133.358,72.778 133.77,72.778 133.925,72.933 U28.J3@133.925,73.55
DDR_DQ25: U27.G22 U28.H2 | length 39.7
  Top Layer w0.09: U27.G22@102.4,76 102.41,75.99 102.904,75.99 103.068,75.826 122.099,75.826 126.009,71.916 126.264,71.916 126.52,72.173 126.52,72.54 126.75,72.77 127.755,72.77 128.03,72.495 128.03,72.249 128.134,72.145 128.7,72.145 128.8,72.245 128.8,72.52 129.05,72.77 129.84,72.77 130.016,72.595 130.016,72.21 130.08,72.145 130.88,72.145 130.935,72.2 130.935,72.824 131.021,72.91 131.816,72.91 131.925,72.8 131.925,72.398 131.998,72.325 132.131,72.325 132.3,72.495 132.3,72.85 132.36,72.91 132.554,72.91 132.61,72.853 132.61,72.415 132.7,72.325 132.835,72.325 133.015,72.145 133.135,72.145 133.478,72.488 133.89,72.488 134.093,72.69 134.267,72.69 134.425,72.849 134.425,73.275 134.329,73.371 134.329,73.929 U28.H2@134.725,74.325
DDR_DQ26: U27.G21 U28.H3 | length 40.5
  Top Layer w0.09: U27.G21@101.6,76 101.9,76 102.2,75.7 102.784,75.7 102.948,75.536 121.969,75.536 126.18,71.325 126.66,71.325 126.81,71.475 126.81,72.363 126.904,72.457 127.632,72.457 127.74,72.349 127.74,71.956 127.841,71.855 128.977,71.855 129.1,71.978 129.1,72.307 129.268,72.475 129.601,72.475 129.726,72.35 129.726,71.951 129.822,71.855 131.03,71.855 131.225,72.05 131.225,72.39 131.319,72.483 131.55,72.483 131.627,72.407 131.627,72.008 131.78,71.855 132.165,71.855 132.345,72.035 132.715,72.035 132.895,71.855 133.255,71.855 133.598,72.198 134.011,72.198 134.213,72.4 135.008,72.4 135.135,72.526 135.135,72.715 134.725,73.124 U28.H3@134.725,73.55
DDR_DQ27: U27.G20 U28.G2 | length 41.6
  Top Layer w0.09: U27.G20@100.8,76 101.1,75.7 101.527,75.7 101.727,75.5 102.574,75.5 102.828,75.246 121.848,75.246 126.543,70.552 126.809,70.552 127.1,70.843 127.1,71.975 127.225,72.1 127.355,72.1 127.45,72.005 127.45,71.715 127.6,71.565 133.375,71.565 133.718,71.908 134.131,71.908 134.328,72.105 135.59,72.105 135.7,72.216 135.7,72.515 135.425,72.791 135.425,73.051 135.18,73.295 135.18,73.98 U28.G2@135.525,74.325
DDR_DQ28: U27.J21 U28.J7 | length 41.5
  Top Layer w0.09: U27.J21@101.6,74.4 101.614,74.4 101.892,74.122 121.368,74.122 126.35,69.14 126.635,69.14 127.45,68.325 127.45,67.601 127.675,67.376 127.675,67.004 127.779,66.9 129.995,66.9 130.152,67.057 130.152,67.502 130.4,67.75 131.301,67.75 131.63,67.421 131.63,66.997 131.728,66.9 133.223,66.9 133.566,67.243 133.858,67.243 134,67.385 134,67.525 133.8,67.725 133.6,67.725 133.505,67.82 133.505,68.86 133.768,69.123 133.898,69.123 133.98,69.205 134.068,69.205 134.303,69.439 134.303,69.973 U28.J7@133.925,70.35
DDR_DQ29: U27.J20 U28.H8 | length 41.8
  Top Layer w0.09: U27.J20@100.8,74.4 101.125,74.4 101.2,74.325 101.2,74 101.368,73.832 121.248,73.832 126.23,68.85 126.515,68.85 127.16,68.205 127.16,67.37 127.385,67.145 127.385,66.884 127.659,66.61 130.312,66.61 130.442,66.74 130.442,67.382 130.52,67.46 131.181,67.46 131.34,67.301 131.34,66.765 131.496,66.61 133.64,66.61 134.5,67.47 134.5,67.775 134.3,67.975 134.3,68.869 134.725,69.294 U28.H8@134.725,69.55
DDR_DQ30: U27.K20 U28.H7 | length 42.5
  Top Layer w0.09: U27.K20@100.8,73.6 100.858,73.542 121.128,73.542 126.11,68.56 126.395,68.56 126.87,68.085 126.87,67.25 127.095,67.025 127.095,66.763 127.539,66.32 130.432,66.32 130.732,66.62 130.732,67.028 130.8,67.096 130.998,67.096 131.05,67.043 131.05,66.584 131.314,66.32 133.795,66.32 135.1,67.625 135.1,69.692 134.725,70.067 U28.H7@134.725,70.35
DDR_DQ31: U27.L19 U28.F7 | length 42.9
  Top Layer w0.09: U27.L19@100,72.8 100.442,73.242 121.018,73.242 126.58,67.68 126.58,66.868 127.419,66.03 133.93,66.03 135.926,68.026 135.926,69.951 U28.F7@136.325,70.35
DDR_DQM0: U27.W21 U29.E7 | length 19.9
  Top Layer w0.09: U27.W21@101.6,66.4 101.921,66.721 102.694,66.721 104.982,64.434 105.459,64.434 106.16,63.732 109.138,63.732 109.706,64.3 118.416,64.3 U29.E7@119.494,63.222
DDR_DQM1: U27.P20 U29.E2 | length 36.9
  Top Layer w0.09: U27.P20@100.8,70.4 101.34,70.4 101.713,70.028 103.22,70.028 103.225,70.033 103.24,70.033 104.304,71.097 120.187,71.097 121.575,69.709 121.575,69.135 121.807,68.904 122.381,68.904 123.495,67.789 123.495,67.402 123.169,67.075 123.169,65.672 123.092,65.595 122.575,65.595 122.491,65.679 122.491,66.034 122.379,66.146 122.228,66.146 122.125,66.042 122.125,65.692 122.028,65.595 120.109,65.595 119.827,65.877 119.627,65.877 118.886,65.136 118.886,64.8 118.787,64.7 118.346,64.7 118.2,64.847 118.2,64.991 119.069,65.86 119.069,66.797 U29.E2@119.494,67.222
DDR_DQM2: U27.E21 U28.E2 | length 53.4
  Top Layer w0.09: U27.E21@101.6,77.6 103.26,77.6 103.76,78.1 103.956,78.1 104.456,77.6 104.83,77.6 105.48,78.25 106.595,78.25 107.279,77.566 107.666,77.566 108.351,78.25 138.1,78.25 141.122,75.228 141.122,74.492 140.803,74.173 140.803,73.793 141.002,73.595 141.002,73.461 140.803,73.263 140.803,72.875 140.683,72.755 140.2,72.755 140.11,72.845 140.11,73.115 139.975,73.25 139.784,73.25 139.625,73.091 139.625,72.9 139.48,72.755 138.162,72.755 137.94,72.532 137.94,71.606 137.844,71.511 137.594,71.511 137.507,71.597 137.507,72.722 137.4,72.829 136.816,72.829 136.703,72.942 136.703,73.923 137.128,74.348 U28.E2@137.125,74.35
DDR_DQM3: U27.H20 U28.E7 | length 42.1
  Top Layer w0.09: U27.H20@100.8,75.2 100.8,74.898 100.876,74.822 101.616,74.822 101.79,74.648 101.947,74.648 102.183,74.412 121.488,74.412 126.47,69.43 126.755,69.43 127.285,68.9 127.421,68.9 127.53,69.01 127.53,69.335 127.965,69.769 127.965,70.475 127.965,70.491 128.169,70.695 134.353,70.695 134.88,71.222 137.429,71.222 137.525,71.125 137.525,70.725 U28.E7@137.125,70.325
DDR_DQS0_N: U27.W20 U29.F3 | length 20.6
  Top Layer w0.09: U27.W20@100.8,66.4 101.082,66.682 101.343,66.682 101.682,67.022 102.804,67.022 105.102,64.724 105.579,64.724 106.28,64.022 109.018,64.022 109.589,64.593 117.252,64.593 118.418,65.758 118.418,66.146 U29.F3@118.694,66.422
DDR_DQS0_P: U27.V20 U29.G3 | length 20.2
  Top Layer w0.09: U27.V20@100.8,67.2 101.068,66.932 101.239,66.932 101.579,67.272 102.907,67.272 105.205,64.974 105.682,64.974 106.384,64.272 108.914,64.272 109.486,64.843 117.149,64.843 118.168,65.862 118.168,66.141 117.894,66.415 U29.G3@117.894,66.422
DDR_DQS1_N: U27.N21 U29.A7 | length 36.6
  Top Layer w0.09: U27.N21@101.6,71.2 101.6,70.904 101.936,70.568 102.996,70.568 104.066,71.637 120.411,71.637 124.035,68.013 124.035,66.556 123.733,66.254 123.733,65.462 123.303,65.032 119.551,65.032 119.426,64.907 119.426,64.707 119.544,64.59 122.12,64.59 122.41,64.3 122.41,63.506 U29.A7@122.694,63.222
DDR_DQS1_P: U27.N20 U29.B7 | length 36.9
  Top Layer w0.09: U27.N20@100.8,71.2 101.07,70.93 101.22,70.93 101.833,70.318 103.1,70.318 104.169,71.387 120.307,71.387 123.785,67.909 123.785,66.66 123.483,66.358 123.483,65.565 123.2,65.282 119.448,65.282 119.176,65.01 119.176,64.604 119.44,64.34 122.016,64.34 122.16,64.196 122.16,63.502 U29.B7@121.882,63.224
DDR_DQS2_N: U27.D22 U28.A7 | length 51.7
  Top Layer w0.09: U27.D22@102.4,78.4 102.461,78.4 102.581,78.52 102.836,78.52 103.397,79.08 138.444,79.08 141.953,75.571 141.953,71.39 141.57,71.008 140.936,71.008 140.625,71.318 140.625,71.675 140.377,71.923 139.096,71.923 138.972,71.8 138.972,71.398 139.09,71.28 139.849,71.28 140.058,71.071 140.058,70.592 U28.A7@140.325,70.325
DDR_DQS2_P: U27.D21 U28.B7 | length 52.2
  Top Layer w0.09: U27.D21@101.6,78.4 101.605,78.395 101.816,78.395 102.111,78.1 102.575,78.1 102.745,78.27 102.94,78.27 103.5,78.83 138.34,78.83 141.703,75.468 141.703,71.494 141.467,71.258 141.04,71.258 140.875,71.422 140.875,71.778 140.481,72.173 138.992,72.173 138.722,71.903 138.722,71.295 138.987,71.03 139.746,71.03 139.808,70.968 139.808,70.658 U28.B7@139.513,70.363
DDR_DQS3_N: U27.H21 U28.F3 | length 41.5
  Top Layer w0.09: U27.H21@101.533,75.175 102.001,75.175 102.47,74.706 121.62,74.706 126.604,69.721 127.379,69.721 127.658,70 127.658,70.723 127.92,70.985 133.983,70.985 134.563,71.565 136.748,71.565 137.064,71.88 137.064,72.236 136.8,72.499 136.552,72.499 136.05,73.001 136.05,73.275 U28.F3@136.325,73.55
DDR_DQS3_P: U27.H22 U28.G3 | length 40.1
  Top Layer w0.09: U27.H22@102.4,75.2 102.4,75.136 102.581,74.956 121.723,74.956 126.708,69.971 127.276,69.971 127.408,70.104 127.408,70.827 127.817,71.235 133.88,71.235 134.46,71.815 136.645,71.815 136.814,71.984 136.814,72.132 136.697,72.249 136.449,72.249 135.8,72.898 135.8,73.275 U28.G3@135.525,73.55
DDR_ODT: R258.1 U27.M17 U28.K3 U29.K3 | length 58.3
  Top Layer w0.09: U27.M17@98.4,72 98.437,72.037 98.437,72.211 98.625,72.4 v2(98.7,72.4) ; U29.K3@115.494,66.422 115.508,66.422 115.9,66.814 v4(115.9,66.848) ; U28.K3@133.125,73.525 133.14,73.525 133.525,73.911 v4(133.525,73.95)
  Bottom Layer w0.09: v2(98.7,72.4) 98.7,75.362 98.635,75.427 98.635,75.798 99.508,76.671 106.958,76.671 110.877,72.752 111.149,72.752 115.058,68.843 115.058,68.323 115.5,67.881 115.5,67.324 115.745,67.078 115.745,67.042 115.9,66.887 115.9,66.825 115.925,66.825 116.91,67.81 117.704,67.81 118.131,68.236 118.131,68.987 ; 118.131,68.987 118.504,69.36 118.504,69.673 118.505,69.674 ; 118.505,69.676 127.016,78.187 130.992,78.187 132.852,76.327 132.852,75.523 133.12,75.255 133.12,74.596 133.362,74.355 133.455,74.355 133.525,74.285 v4(133.525,73.95) 133.674,73.95 133.728,74.005 133.954,74.005 134.354,74.405 135.124,74.405 136.15,75.431 R258.1@136.15,77.175
DDR_RASN: R276.1 U27.N17 U28.L8 U29.L8 | length 55.7
  Top Layer w0.09: U27.N17@98.4,71.2 v2(98.775,70.825) ; v4(114.3,62.025) 114.3,62.055 U29.L8@114.669,62.424 ; v4@131.932,69.158 U28.L8@132.301,69.527
  Bottom Layer w0.09: v2(98.775,70.825) 99.833,70.825 100.178,71.17 101.426,71.17 102.333,70.263 104.029,70.263 104.081,70.21 104.081,69.166 104.43,68.818 105.02,68.818 105.515,68.322 105.515,67.1 105.285,66.87 105.285,66.324 106.42,65.189 106.9,65.189 107.245,65.535 107.555,65.535 108.155,64.935 110.212,64.935 110.54,64.607 112.315,64.607 113.905,63.017 113.905,62.589 114.064,62.43 114.195,62.43 114.275,62.35 114.275,62.05 v4(114.3,62.025) 114.636,62.025 115.191,61.47 117.045,61.47 117.69,62.115 118.584,62.115 119.459,62.99 120.432,62.99 121.371,63.929 122.3,63.929 124.91,66.539 124.91,69.986 126.884,71.96 129.661,71.96 131.276,70.345 131.289,70.345 131.52,70.114 131.52,70.101 131.53,70.091 131.53,69.786 131.762,69.555 131.87,69.555 131.925,69.5 v4(131.925,69.15) 132.526,68.549 133.26,68.549 133.495,68.314 133.495,68.046 133.737,67.805 133.75,67.805 133.75,67.804 134.928,67.804 135.217,67.515 135.702,67.515 136.692,66.525 R276.1@136.725,66.525
DDR_RESETN: R252.2 U27.F18 U28.P1 U29.P1 | length 56.4
  Top Layer w0.09: U27.F18@99.2,76.8 99.22,76.82 99.495,76.82 99.575,76.9 99.575,77 ; 99.575,77 v2(99.575,77.325) ; 112.05,69.6 112.15,69.7 117.543,69.7 117.718,69.525 v4(117.8,69.525) ; 112.05,69.604 112.05,68.265 U29.P1@112.294,68.022 ; U28.P1@129.925,75.15 129.602,75.474 129.602,76.533 129.869,76.8 133.4,76.8 v4(133.525,76.675)
  Bottom Layer w0.09: v2(99.575,77.325) 107.764,77.325 114.339,70.75 117.353,70.75 117.8,70.303 ; v4(117.8,69.525) 117.8,70.303 ; v4(133.525,76.675) 133,77.2 132.9,77.2 132.025,78.075 R252.2@132.025,78.4 131.886,78.4 131.246,79.04 126.538,79.04 117.8,70.303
